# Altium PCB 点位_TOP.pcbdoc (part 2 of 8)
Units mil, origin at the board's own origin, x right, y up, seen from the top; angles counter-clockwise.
Board outline 5129 x 4161 mil, 8 copper layers (Top Layer, GND1, 内层2, VCC, 内层4, Inner5, GND2, Bottom Layer); 288 components, 452 nets, 2040 pads, 1119 vias.
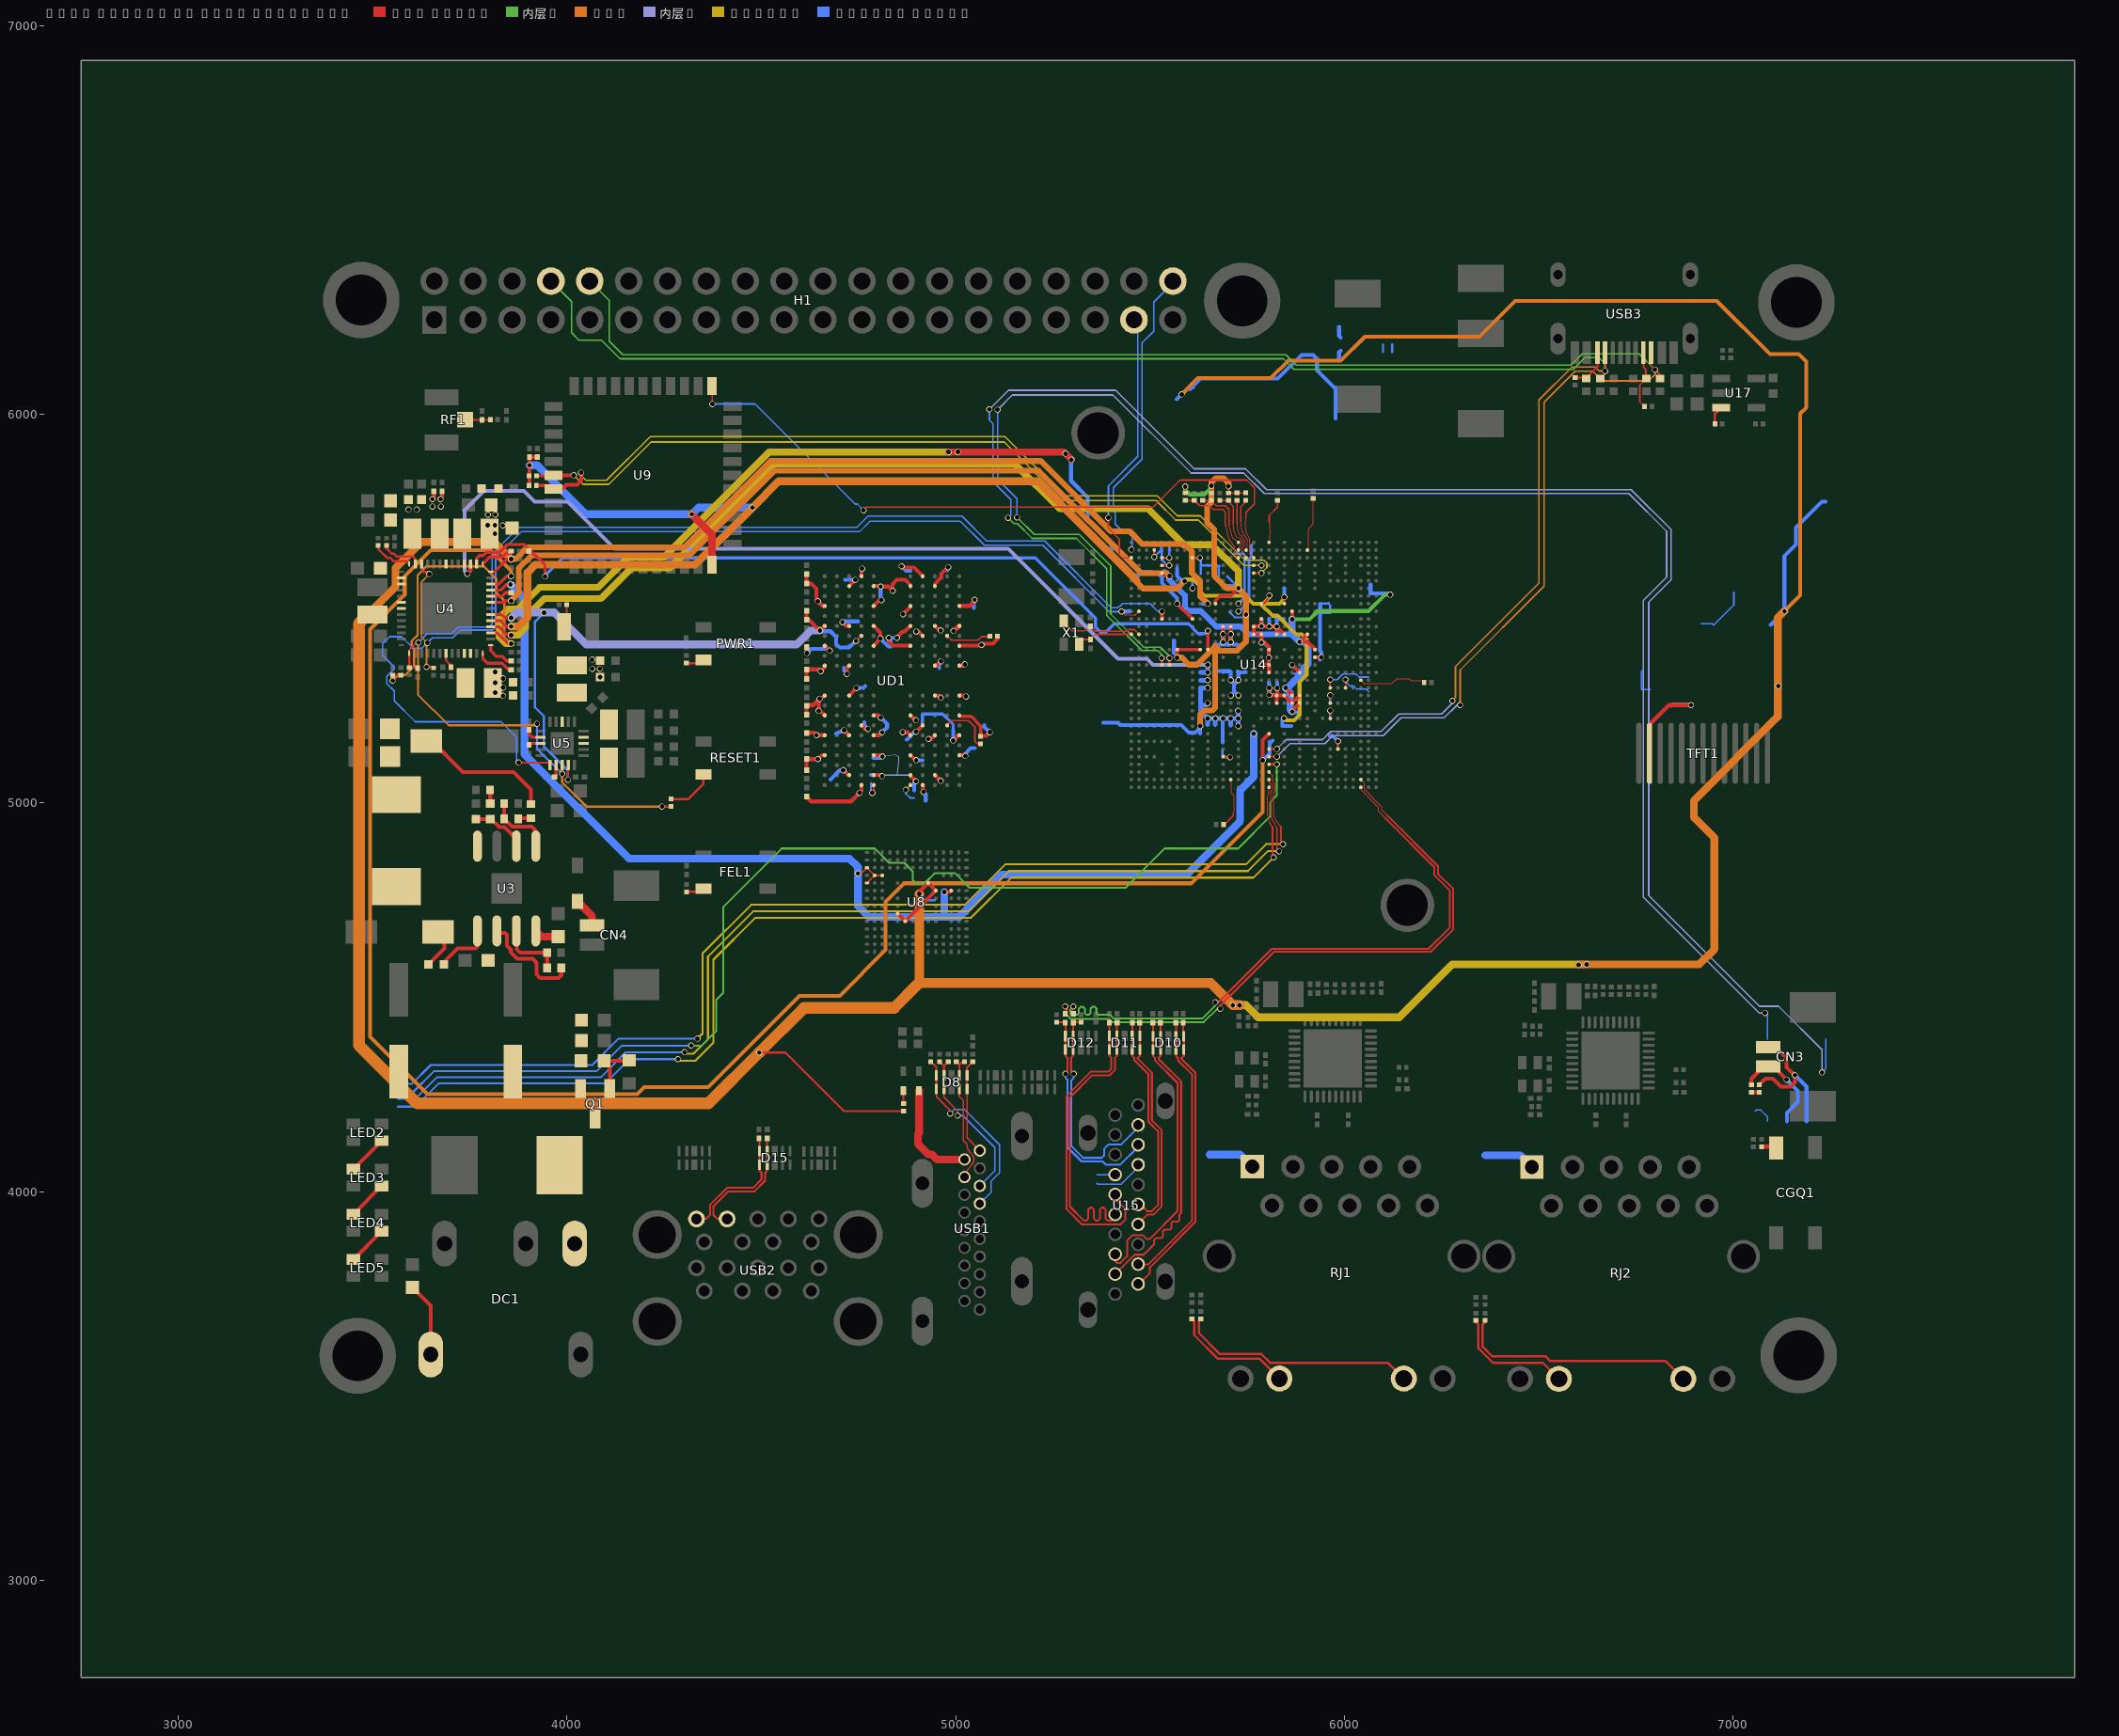
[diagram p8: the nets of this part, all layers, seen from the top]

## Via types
v1: diameter 15.75, hole 11.8, Top Layer to Bottom Layer, 496 vias
v2: diameter 15.7, hole 11.8, Top Layer to Bottom Layer, 335 vias
v3: diameter 15.75, hole 11.81, Top Layer to Bottom Layer, 279 vias
v4: diameter 24, hole 12, Top Layer to Bottom Layer, 9 vias

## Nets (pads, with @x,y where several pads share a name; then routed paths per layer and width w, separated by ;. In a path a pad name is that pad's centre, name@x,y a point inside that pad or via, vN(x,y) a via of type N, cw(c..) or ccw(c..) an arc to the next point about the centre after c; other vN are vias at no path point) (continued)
323-DCDC3: C87.2 C89.2 L8.2 U14.AA12 U14.AA13 U14.Y12 U14.Y13 | length 199.1
  Top Layer w10: v2(5688.24,5414.21) v2(5688.24,5434.21) U14.AA12@5688.24,5453.9 ; v2(5707.92,5414.21) v2(5707.92,5434.21) U14.Y12@5707.92,5453.9
  Bottom Layer w10: 5667.23,5407.31 v2@5686.23,5407.31 ; v2(5688.24,5434.21) v2(5688.24,5414.21) 5688.24,5409.32 v2@5686.23,5407.31 ; v2@5704.99,5407.14 5707.92,5410.07 v2(5707.92,5414.21) ; v2(5707.92,5434.21) v2(5707.92,5414.21) ; 5725.23,5407.31 5714.83,5407.31 v2(5707.92,5414.21) ; v2@5686.23,5407.31 5701.02,5407.31 v2(5707.92,5414.21)
  other v1: 4084.95,5323.63 4065,5345.34 4085.38,5345.34 4065,5369
323-DLDO1: C71.1 U5.12 | length 32.6
  Top Layer w8: C71.1@3968.5,5067 3972.09,5070.59 U5.12@3972.09,5098.08
323-RTCLDO: C73.1 U5.7 | length 43.8
  Top Layer w8: C73.1@3903,5188 3903,5177 3911,5169 3932.19,5169 U5.7@3932.43,5169.24
$1N3706: L2.1 U4.10 U4.11
$1N3718: L3.1 U4.33
$1N3723: L4.1 U4.30
$1N3725: C43.1 U4.7 | length 41.6
  Top Layer w6: U4.7@3689.11,5385.61 3689.11,5366.89 3701.75,5354.25 C43.1@3701.75,5349.22
$1N4703: R13.2 U4.39 | length 104.9
  Top Layer w6: R13.2@3514.47,5662.49 3514.47,5653.53 3537,5631 3545.49,5631 3554.49,5622 3587.96,5622 U4.39@3594.63,5615.33
$1N4773: C44.2 U4.41 U4.42
$1N4806: R14.2 U4.38 | length 105.5
  Top Layer w6: R14.2@3536,5662.49 3536,5655 3549,5642 3554,5642 3561.5,5634.5 3603.5,5634.5 3610.37,5627.63 U4.38@3610.37,5615.33
$1N4992: L5.2 U4.45 U4.46
$1N6251: L6.1 U5.18
$1N6517: L7.1 U5.19
$1N6728: L8.1 U5.3
$1N7320: C88.1 U5.8 | length 31.1
  Top Layer w8: C88.1@3903,5149.5 3906.99,5153.49 U5.8@3932.43,5153.49
$1N42597: LED1.1 R17.1 | length 59
  Top Layer w6: LED1.1@3992.63,5453.84 3999.51,5460.73 R17.1@3999.51,5510
$2N1846: R21.1 RESET1.3 | length 123.8
  Top Layer w6: R21.1@4268,5010.51 4312.51,5010.51 4351.32,5049.32 RESET1.3@4351.32,5073.68
$2N2360: R19.1 U14.V3 | length 162.3
  Top Layer w3: 5725.01,5720.45 5726.4,5700.33 5731.46,5688.13 5735.46,5687.29 5743.72,5675.93 5743.82,5663.67 5737.3,5657.15 5737.36,5656.88 5737.36,5640.84 U14.V3@5747.19,5631.01
  Top Layer w4: R19.1@5724.27,5778.76 5724.27,5720.73 5725,5720
$2N2431: R20.1 U14.V2 | length 136.5
  Top Layer w3: 5734,5724.93 5736.55,5705.39 5741.89,5689.5 5750.21,5678.07 5750.31,5665.03 5750.55,5664.3 5750.55,5662.51 U14.V2@5746.51,5651.79
  Top Layer w4: 5734,5725 5734,5762 5746.27,5774.27 R20.1@5746.27,5778.76
$2N32401: FEL1.3 R22.1 | length 46.7
  Top Layer w6: R22.1@4308,4771.49 4343.13,4771.49 FEL1.3@4351.32,4779.68
$2N32457: PWR1.3 R23.1 | length 47.4
  Top Layer w6: R23.1@4307.07,5360.18 4343.82,5360.18 PWR1.3@4351.32,5367.68
$3N7591: U14.AA29 | length 51.6
  Top Layer w4.5: U14.AA29@5687.91,5119.12 5688.77,5118.26 v3(5706.21,5118.26)
  Bottom Layer w6: 5685.92,5135.46 5686.92,5134.46 5686.92,5124.97 5693.63,5118.26 v3(5706.21,5118.26)
$3N7643: UD1.A5 | length 53.9
  Top Layer w4.5: v3(4871.92,5033.97) 4883.64,5045.69 UD1.A5@4883.64,5046.54
  Bottom Layer w4.5: v3(4871.92,5033.97) 4871.92,5023.97 4882.76,5013.13 4893.92,5013.13
$3N7644: UD1.A8 | length 49.9
  Top Layer w4.5: v3(4785.84,5025.97) 4789.16,5029.29 UD1.A8@4789.16,5046.54
  Bottom Layer w4.5: 4782.21,5052.45 4782.21,5029.6 v3(4785.84,5025.97)
$3N7648: R36.1 UD1.G2 | length 138
  Top Layer w4.5: UD1.G2@4978.13,5200.08 4990.04,5212 5033,5212 5049.92,5195.08 5049.92,5157.63 5054.42,5153.13 R36.1@5064.92,5153.13
$3N7649: R37.1 UD1.T2 | length 119
  Top Layer w4.5: UD1.T2@4978.13,5430.4 4989.56,5418.97 5057.92,5418.97 5066.92,5427.97 5086.08,5427.97 R37.1@5087.92,5429.81
$4N500: R41.2 U14.Y32 | length 129.9
  Top Layer w3: U14.Y32@5709.98,5059.57 5709.98,5025.76 5716.84,5018.9 5716.84,4985.06 5714.63,4973.87
  Top Layer w4: R41.2@5689.66,4944.85 5691.85,4944.85 5714.54,4967.54 5714.54,4974.38
$4N609: R42.1 U14.C19 | length 176.1
  Top Layer w3: U14.C19@6042.49,5316.01 6052.39,5306.11 6121.11,5306.11 6133.9,5318.9 6167.81,5318.9 6172.71,5314 6201.49,5314 R42.1@6205.49,5310
$4N713: R43.1 U14.R1 | length 119
  Top Layer w3: U14.R1@5806.29,5670.41 5807.09,5671.21 5810.05,5698.92 5809.6,5700.66 5807,5723.72 5806.92,5724.41 ; 5807,5722.99 5807.09,5722.9
  Top Layer w4: 5807,5722.99 5807,5723.72 5807,5740 5828,5761 R43.1@5828,5778.49
$5N3909: R123.2 U14.K2 | length 139.1
  Top Layer w3: U14.K2@5904.69,5650.71 5908.43,5654.45 5908.43,5705.75 5920,5717.32 R123.2@5920,5783.49
$6N1044: U14.G22 | length 38.7
  Top Layer w4: U14.G22@5963.82,5257.04 v1(5963.82,5277.04)
  Bottom Layer w6: 5963.49,5258.47 5963.82,5258.8 v1(5963.82,5277.04)
$6N1104: U14.G24 | length 39.8
  Top Layer w4: U14.G24@5963.82,5217.67 v1(5963.82,5237.67)
  Bottom Layer w6: 5963.49,5218 5963.49,5237.33 v1(5963.82,5237.67)
$6N1424: U14.F28 | length 45.2
  Top Layer w4: U14.F28@5983.52,5138.93 v1(5983.52,5158.93)
  Bottom Layer w10: 5963.51,5171.53 5970.91,5171.53 v1(5983.52,5158.93)
$6N1887: U14.G20 | length 129
  Top Layer w4: U14.G20@5963.83,5296.4 v1(5963.83,5317.4)
  Bottom Layer w4: v1(5963.83,5317.4) 5981.4,5317.4 5996,5332 6030,5332 6038,5324 6062.49,5324
$6N1980: U14.E20 | length 97.6
  Top Layer w4: U14.E20@6003.2,5296.41 v1(6003.2,5317.41)
  Bottom Layer w4: v1(6003.2,5317.41) 6003.2,5311.8 6014,5301 6024,5301 6032,5293 6056.49,5293 6063.49,5286
$6N3848: D7.2 R47.2 | length 33.5
  Top Layer w5: R47.2@4866,4226.51 D7.2@4866,4260
$6N3980: D8.1 D8.10 R48.2 USB1.13 | length 496.1
  Top Layer w4: D8.1@4950.63,4264.67 4950.63,4244.37 4986,4209 v1(4986,4201)
  Top Layer w5: R48.2@4936,4334.49 4950.63,4319.86 D8.10@4950.63,4299.33 D8.1@4950.63,4264.67
  Bottom Layer w4: v1(4986,4201) 4997,4212 5022,4212 5113,4121 5113,4049 5091,4027 5091,3998.11 USB1.13@5062.26,3969.36
$6N4130: D9.1 USB1.18 | length 274.7
  Top Layer w20: D9.1@4906,4260 4906,4151 4903,4148 4903,4123 4930,4096 4939,4096 4951.97,4083.03 USB1.18@5022.89,4083.03
$6N4341: D8.2 D8.9 R50.2 R52.2 USB1.15 | length 418.4
  Top Layer w4: D8.2@4970.3,4264.67 4970.3,4242.7 5005,4208 v1(5005,4196)
  Top Layer w5: R50.2@4959,4334.49 4970.3,4323.19 ; D8.2@4970.3,4264.67 D8.9@4970.3,4299.33 4970.3,4323.19 ; R52.2@4981,4334.49 4970.3,4323.79 4970.3,4323.19
  Bottom Layer w4: v1(5005,4196) 5019,4196 5101,4114 5101,4053.59 USB1.15@5062.26,4014.85
$6N4352: D8.4 D8.7 R51.2 R53.2 USB1.16 | length 336.3
  Top Layer w4: D8.4@5009.7,4264.67 5009.7,4245.3 5020,4235 5020,4132 5026.32,4125.68 cw(c5011.57,4114.53) 5030,4116 ccw(c5050.64,4117.64) 5036,4103 cw(c4999,4066) 5046,4089 cw(c5033.74,4083) 5046,4077 cw(c5009.34,4094.94) 5040,4068 ccw(c5103.16,4012.51) USB1.16@5022.89,4037.52
  Top Layer w5: R51.2@5002,4334.49 5009.7,4326.79 ; D8.4@5009.7,4264.67 D8.7@5009.7,4299.33 5009.7,4326.79 ; R53.2@5023,4334.49 5017.4,4334.49 5009.7,4326.79
$6N4414: D8.5 D8.6 R54.2 USB1.19 | length 248.4
  Top Layer w4: D8.5@5029.37,4264.68 5029.37,4138.68 USB1.19@5062.26,4105.79
  Top Layer w5: D8.5@5029.37,4264.68 D8.6@5029.37,4299.33 5029.37,4319.86 R54.2@5044,4334.49
$6N5317: C190.2 D10.1 D10.10 U15.1 | length 752.3
  Top Layer w5: U15.1@5469.51,3762.25 5471.41,3762.25 5500.01,3790.85 5500.01,3805.1 5617.01,3922.1 5617.01,4305.81 5581.2,4341.62 5581.2,4344.12 5586.52,4349.45 ; C190.2@5585.6,4435.1 5585.6,4401.06 D10.1@5586.52,4400.14 ; 5587.52,4349.6 D10.1@5587.52,4400.14
$6N5400: C191.2 D10.2 D10.9 U15.3 | length 711.8
  Top Layer w5: U15.3@5469.51,3813.45 5496.45,3813.45 5607.99,3924.99 5607.99,4302.08 5572.18,4337.89 5572.18,4344.12 5566.85,4349.45 D10.9@5566.85,4365.34 ; C191.2@5566.6,4435.1 5566.85,4434.86 D10.2@5566.85,4400.14 D10.9@5566.85,4365.48
$6N5519: C192.2 D10.4 D10.7 U15.4 | length 782.1
  Top Layer w5: U15.4@5410.51,3787.85 5460.51,3837.85 5483.85,3837.85 5511,3865 5511,3876 5516.1,3881.1 5530.1,3881.1 5533.71,3884.71 5533.71,3898.71 5537.32,3902.32 5551.32,3902.32 5554.92,3905.92 5554.92,3919.92 5558.53,3923.53 5572.53,3923.53 5576.14,3927.14 5576.14,3941.14 5580.01,3945.01 5580.01,4283.74 5522.13,4341.62 5522.13,4344.12 5527.45,4349.45 D10.7@5527.45,4365.34 ; C192.2@5526.6,4435.1 5527.45,4434.26 D10.4@5527.45,4400.14 D10.7@5527.45,4365.48
$6N5561: C193.2 D10.5 D10.6 U15.6 | length 778.3
  Top Layer w5: U15.6@5410.51,3839.05 5410.51,3821.35 5415.01,3816.85 5424.01,3816.85 5441.01,3833.85 5441.01,3873.85 5455.36,3888.2 5481.66,3888.2 5491.89,3877.97 5498.97,3877.97 5570.99,3949.99 5570.99,4280.01 5513.11,4337.89 5513.11,4344.12 5507.78,4349.45 D10.6@5507.78,4365.34 ; C193.2@5507.6,4435.1 5507.78,4434.93 D10.5@5507.78,4400.13 D10.6@5507.78,4365.48
$6N5603: C194.2 D11.1 D11.10 U15.7 | length 581.3
  Top Layer w5: U15.7@5469.51,3915.75 5469.51,3917.34 5493.01,3940.84 5508.74,3940.84 5530.01,3962.1 5530.01,4158.85 5505.01,4183.85 5505.01,4305.81 5468.79,4342.03 5468.79,4344.53 5474.11,4349.86 D11.10@5474.11,4365.75 ; C194.2@5473.6,4435.1 5474.1,4434.6 D11.1@5474.1,4400.56 D11.10@5474.1,4365.9
$6N5645: C195.2 D11.2 D11.9 U15.9 | length 561.9
  Top Layer w5: D11.9@5454.44,4365.75 5454.44,4349.86 5459.77,4344.53 5459.77,4338.3 5495.99,4302.08 5495.99,4180.12 5520.99,4155.12 5520.99,3965.84 5505.01,3949.85 5493.01,3949.85 5475.91,3966.95 U15.9@5469.51,3966.95 ; D11.9@5454.43,4365.9 D11.2@5454.43,4400.56 5454.43,4434.93 C195.2@5454.6,4435.1
$6N5687: C196.2 D11.4 D11.7 U15.10 | length 800.3
  Top Layer w5: U15.10@5410.51,3941.35 5410.51,3934.35 5402.01,3925.85 5391.01,3925.85 5386.01,3930.85 5386.01,3953.85 5381.01,3958.85 5376.01,3958.85 5371.01,3953.85 5371.01,3930.85 5366.01,3925.85 5361.01,3925.85 5356.01,3930.85 5356.01,3953.85 5351.01,3958.85 5346.01,3958.85 5341.01,3953.85 5341.01,3930.85 5336.01,3925.85 5330.01,3925.85 5294.01,3961.85 5294.01,4242.1 5351.74,4299.84 5396.74,4299.84 5409.72,4312.81 5409.72,4344.53 5415.04,4349.86 D11.7@5415.04,4365.75 ; D11.7@5415.03,4365.9 D11.4@5415.03,4400.56 5415.03,4434.53 C196.2@5415.6,4435.1
$6N5729: C197.2 D11.5 D11.6 U15.12 | length 804.3
  Top Layer w5: D11.6@5395.37,4365.75 5395.37,4349.86 5400.7,4344.53 5400.7,4316.54 5393.01,4308.85 5348.01,4308.85 5284.99,4245.84 5284.99,3956.01 5325.15,3915.85 5424.01,3915.85 5437.01,3928.85 5437.01,3954.85 5410.51,3981.35 U15.12@5410.51,3992.55 ; D11.6@5395.36,4365.9 D11.5@5395.36,4400.55 5395.36,4434.86 C197.2@5395.6,4435.1
$6N6451: C199.2 D12.2 D12.9 R61.2 U15.17 | length 579.2
  Top Layer w5: v1(5304,4303) 5304,4303.4 5296.97,4310.42 5296.97,4344.46 5302.3,4349.78 D12.2@5302.3,4365.67 D12.9@5302.3,4400.33 5302.3,4434.3 C199.2@5303,4435 5304.49,4436.49 R61.2@5323,4436.49
  Bottom Layer w5: v1(5304,4303) 5304,4292.63 5298,4286.63 5298,4117 5328,4087 5376,4087 5382,4093 5382,4110 5393,4121 5425,4121 5469.5,4165.5 U15.17@5469.5,4171.8
$6N6466: C198.2 D12.1 D12.10 R62.2 U15.15 | length 574.7
  Top Layer w5: R62.2@5260,4436.49 5280.51,4436.49 C198.2@5282,4435 5282.63,4434.37 D12.10@5282.63,4400.33 D12.1@5282.63,4365.67 5282.63,4349.78 5287.96,4344.46 5287.96,4310.42 5283,4305.47 v1(5283,4303)
  Bottom Layer w5: v1(5283,4303) 5283,4292.63 5288,4287.63 5288,4114.25 5324.27,4077.98 5378.02,4077.98 5387,4069 5423,4069 5469.5,4115.5 U15.15@5469.5,4120.7
$6N6553: U15.14 | length 47.1
  Bottom Layer w4: 5363.51,4043.53 5410.14,4043.53 U15.14@5410.5,4043.9
$6N6556: U15.13 | length 132.1
  Bottom Layer w4: 5363.51,4021.53 5366.05,4019 5426,4019 5469.5,4062.5 U15.13@5469.5,4069.5
$6N19248: C220.2 D15.5 D15.6 USB2.18 | length 333
  Top Layer w5: USB2.18@4333.52,3929.89 4357.87,3929.89 4367.98,3940 4367.98,3965.98 4412,4010 4479,4010 4500.96,4031.96 4500.96,4048.46 4495.63,4053.78 D15.6@4495.63,4069.67 D15.5@4495.63,4104.32 4495.63,4135.87 C220.2@4494.25,4137.25
$6N19249: C219.2 D15.4 D15.7 USB2.17 | length 333.2
  Top Layer w5: USB2.17@4412.26,3929.89 4387.11,3929.89 4377,3940 4377,3962.25 4415.73,4000.98 4482.73,4000.98 4509.97,4028.22 4509.97,4048.46 4515.3,4053.78 D15.7@4515.3,4069.67 D15.4@4515.3,4104.33 C219.2@4515.3,4137.2
$6N30377: R117.1 U17.3 | length 48.5
  Top Layer w6: R117.1@6953.26,5975.66 6953.26,6001.84 U17.3@6969.04,6017.62
$8N2040:  | length 139.3
  Bottom Layer w4: 6918,5461 6946.4,5461 6950,5457.4 7001.91,5509.31 7001.91,5541.73
$8N6741: LED2.1 LED3.3 | length 102.8
  Top Layer w10: LED3.3@3451.16,4058.17 3523.21,4130.22 LED2.1@3523.21,4131.12
$8N6795: LED3.1 LED4.3 | length 102.8
  Top Layer w10: LED4.3@3451.16,3941.91 3451.16,3942.81 LED3.1@3523.21,4014.86
$8N6805: LED4.1 LED5.3 | length 102.8
  Top Layer w10: LED5.3@3451.16,3825.65 3523.21,3897.7 LED4.1@3523.21,3898.6
$8N9148:  | length 71.3
  Bottom Layer w4: 6766.11,5340.31 6765,5339.2 6765,5291.51 6787,5291.51
$8N11462: TFT1.12 | length 253.2
  Top Layer w10: TFT1.12@6784.2,5128.67 6784.2,5201.2 6835,5252 v2(6892,5252)
  Bottom Layer w10: 6841,5250 6843,5252 v2(6892,5252)
$10N1043: RJ1.P1 | length 123.4
  Bottom Layer w20: 5653,4095.7 5732.06,4095.7 RJ1.P1@5763.4,4064.36
$10N3488: R79.2 RJ1.12 | length 309.3
  Top Layer w6: R79.2@5608,3672.49 5614,3666.49 5614,3631 5674,3571 5781.16,3571 RJ1.12@5833,3519.16
$10N3497: R80.1 RJ1.13 | length 614
  Top Layer w6: R80.1@5631,3672.49 5631,3671 5626,3666 5626,3636 5680,3582 5787,3582 5809,3560 6112.16,3560 RJ1.13@6153,3519.16
$11N1789: RJ2.P1 | length 131.9
  Bottom Layer w20: 6363,4093.7 6452.3,4093.7 RJ2.P1@6482.4,4063.6
$11N1876: R97.2 RJ2.12 | length 313.9
  Top Layer w6: R97.2@6338.37,3668.61 6338.37,3664.63 6345,3658 6345,3597 6382,3560 6510.4,3560 RJ2.12@6552,3518.4
$11N1882: R98.1 RJ2.13 | length 620.5
  Top Layer w6: R98.1@6362.37,3668.61 6362.37,3664.37 6356,3658 6356,3601 6381,3576 6518,3576 6530,3564 6826.4,3564 RJ2.13@6872,3518.4
$12N612: D2.2 DC1.1 Q1.3
$12N673: Q1.1 R1.1 R2.2 | length 142.2
  Top Layer w10: Q1.1@4110.4,4265.37 4110.4,4322.26 R1.1@4095.66,4337 4159.66,4337 R2.2@4160,4336.66
$12N750: C3.2 DC1.5 | length 191.9
  Top Layer w10: C3.2@3603,3753.47 3650.09,3706.39 DC1.5@3650.09,3581.04
$12N1163: C4.1 U3.1 | length 148.6
  Top Layer w10: C4.1@3683.99,4585 3683.99,4590.99 3719,4626 3765,4626 3770,4631 U3.1@3770,4670.98
$12N1491: C8.2 U3.4 | length 64
  Top Layer w20: U3.4@3920,4670.98 3934.51,4656.47 C8.2@3978,4656.47
$12N1559: C4.2 D4.2 L1.1 U3.8 | length 106.8
  Top Layer w10: C4.2@3643.99,4585 3685,4626.01 3685,4651.57 D4.2@3668.57,4668
$12N1618: C9.1 C10.1 U3.6 | length 144.9
  Top Layer w10: C10.1@3766,4959.01 C9.1@3803,4959.01 3804,4960 3826,4938 3840,4938 3870,4908 U3.6@3870,4889.02
$12N1697: C9.2 R7.1 | length 35.4
  Top Layer w10: R7.1@3802,5034 3803,5032.99 C9.2@3803,4999.01
$12N1966: R3.1 R5.2 | length 33.9
  Top Layer w10: R5.2@3874.85,4959.19 3876.66,4961 R3.1@3908,4961
$12N2016: R5.1 R8.2 U3.5 | length 172.6
  Top Layer w10: R8.2@3838.85,4998.18 R5.1@3838.85,4959.19 3859.04,4939 3910,4939 3920,4929 U3.5@3920,4889.02
$12N2052: R4.1 R6.2 U3.3 | length 168.6
  Top Layer w10: U3.3@3870,4670.98 3871,4669.98 3871,4624 3880.22,4614.78 R6.2@3949.27,4614.78 3949.27,4575.95 R4.1@3949.45,4575.77
$12N3300: CN4.2 D1.1 | length 77.7
  Top Layer w20: D1.1@4027,4746.84 4064.91,4708.92 CN4.2@4064.91,4684.8
$13N975: C245.2 R72.2 RF1.1 | length 65.1
  Top Layer w5: RF1.1@3738.02,5986 3738.24,5986.22 C245.2@3781.57,5986.22 R72.2@3803.06,5986.22
$13N1231:  | length 51.1
  Bottom Layer w4: 7057,4207.51 7059.49,4210 7071,4210 7089,4192 7089,4181.39
$13N1378: R77.1 R78.1 | length 20.1
  Top Layer w10: R77.1@7047.19,4255.75 7067.17,4255.75 R78.1@7067.26,4255.83
$13N1478: CN3.1 R77.2 | length 263.9
  Top Layer w10: R77.2@7047.19,4274.77 7047.19,4290.19 7079.2,4322.2 CN3.1@7090.91,4322.2 7103.8,4322.2 v2(7138,4288)
  Bottom Layer w10: v2(7138,4288) 7167,4259 7167,4231 7139,4203 7139,4181.39
$13N1485: CN3.2 R78.2 | length 373.6
  Top Layer w10: R78.2@7067.26,4274.85 7083.4,4291 7102,4291 7123,4270 7148,4270 7159,4281 v2(7159,4300) 7158,4300 7138,4320 7138,4344 7110.2,4371.8 CN3.2@7090.91,4371.8
  Bottom Layer w10: v2(7159,4300) 7189,4270 7189,4181.39
$13N1600:  | length 20.8
  Bottom Layer w5: 6123.19,6180.04 6123.19,6160.06 6123.76,6159.49
$13N1603:  | length 21.5
  Bottom Layer w5: 6099.76,6159.49 6099.76,6180.98
$13N2020:  | length 27.6
  Bottom Layer w10: 5986.49,6138 5986.49,6159.62 5990.72,6163.85
$13N2077:  | length 28.9
  Bottom Layer w10: 5986.49,6225 5986.49,6202.51 5990.99,6198
$13N5258: CGQ1.4 R125.1 | length 38.6
  Top Layer w10: R125.1@7073.62,4115.95 7107.74,4115.95 CGQ1.4@7110.88,4112.8
ADCIN0: U14.W9 | length 161.6
  Bottom Layer w6: 5716,5642 5736.51,5642 5738,5643.49 5743,5638.49 5743,5528.33
  Bottom Layer w7: v1(5727.62,5512.95) 5743,5528.33
ADCIN1: U14.W10 | length 186.5
  Bottom Layer w7: v1(5727.61,5493.27) 5730.27,5493.27 5755,5518 5755,5628 5760.49,5633.49 5760.49,5662.49 5762,5664
AGND: U14.AE3 | length 137
  Top Layer w6: U14.AE3@5609.5,5631.06 v1(5628.5,5631.06)
  Bottom Layer w6: v1(5628.5,5631.06) 5631.25,5628.31 5631.25,5611.25 ; 5631.25,5589.25 5631.25,5611.25 ; 5676.5,5583 5676.5,5607.51 ; 5679,5610 5676.5,5607.51 ; 5631.25,5611.25 5651.75,5611.25 5652,5611.5 5672.51,5611.5 5676.5,5607.51
ALDO1: C51.1 U4.13 | length 98.3
  Top Layer w8: U4.13@3783.6,5385.61 3784,5385.21 3784,5372 3796,5360 3833,5360 3850,5343 C51.1@3856.5,5343
ALDO2: C52.1 U4.14 | length 77.3
  Top Layer w8: U4.14@3803.97,5405.98 3803.97,5392.03 3819,5377 3834.25,5377 3845.25,5366 C52.1@3856.5,5366
ALDO3: C53.1 R11.1 R12.1 U4.16 U14.AE11 U14.AG9 | length 3149.8
  Top Layer w6: v1(3551.77,5315) R11.1@3551.77,5329.26 R12.1@3572.77,5329.26
  Top Layer w8: U4.16@3803.97,5437.48 3821.52,5437.48 3849,5410 v2(3856.5,5410)
  Top Layer w10: v2(5570.13,5512.95) U14.AE11@5609.5,5473.58
  Top Layer w18: v2(4982,5903) v2(5006,5903) 5279,5903 v2(5283,5899) 5298,5884 v2(5298,5883)
  VCC w6: v1(3551.77,5315) 3565.77,5329 3584,5329 3607,5352 3607,5395 3601,5401 3601,5417 3616,5432 3616,5586 3639,5609 3786,5609 3819,5576 3819,5541 3839,5521 3839,5427.5 v2(3856.5,5410)
  Inner5 w18: v2(3856.5,5410) 3843,5410 3826,5427 3826,5476 3849,5499 3874.46,5499 3930.46,5555 4081,5555 4159,5633 4250.46,5633 4520.46,5903 v2(4982,5903)
  Bottom Layer w10: v2(5298,5883) 5297,5882 5297,5829 5340,5786 5340,5730 5401,5669 5401,5644 5459,5586 5471,5586 5480,5595 5505,5595 5510,5590 5521,5590 5531,5580 5531,5566 5570.13,5526.87 v2(5570.13,5512.95)
ALDO4: C54.1 R19.2 R20.2 R30.2 R31.2 R32.2 U4.17 U14.AB9 U14.AD15 U14.AD25 U14.AG15 U14.W7 | length 4078.8
  Top Layer w4: R32.2@5591,5797.51 v1(5591,5814) ; R30.2@5658,5797.51 v1(5658,5816) ; v1(5702,5815) R31.2@5702,5797.51 R19.2@5724,5797.51 ; R19.2@5724.27,5797.78 R19.2@5724,5797.51 ; R20.2@5746.27,5797.78 5746,5797.51 R19.2@5724,5797.51
  Top Layer w8: U4.17@3803.97,5453.23 3825.77,5453.23 3844,5435 3853.5,5435 v2(3856.5,5432) ; U14.AG15@5570.13,5394.83 U14.AD15@5629.18,5394.84 ; U14.AB9@5668.54,5512.95 5668.54,5520.54 5681,5533 5708.29,5533 v1(5727.62,5552.32)
  Top Layer w10: v2(5570,5374) 5570,5394.71 U14.AG15@5570.13,5394.83
  内层2 w10: v1(5591,5814) 5591,5805 5602,5794 5640,5794 5658,5812 v1(5658,5816)
  VCC w15: v2(5570,5374) 5582,5374 5599.89,5356.11 5621.11,5356.11 5668,5403 ; v1(5629.19,5197.99) 5629.19,5228.19 5639,5238 5660,5238 5668,5246 5668,5403 ; v1(5702,5815) 5702,5823 5689,5836 5670,5836 5658,5824 v1(5658,5816) 5658,5773 5647,5762 5647,5722 5665,5704 5665,5585 5697.68,5552.32 v1(5727.62,5552.32) 5747,5532.94 v2(5747,5484.84) 5747,5415 5724,5392 5679,5392 5668,5403
  Inner5 w18: v2@3856.6,5432.1 3856.7,5432 3875,5432 3894,5451 3894,5478 3942,5526 4087,5526 ; 4090,5528 4167,5605 4265.46,5605 4533.46,5873 5152,5873 5268,5757 5495,5757 5587,5665 5659,5665 5727.62,5596.38 v1(5727.62,5552.32)
  Bottom Layer w5: 5704.51,5491 5717.51,5478 5740.16,5478 v2(5747,5484.84)
  Bottom Layer w6: 5699,5583 5727.62,5554.38 v1(5727.62,5552.32)
  Bottom Layer w8: 5699,5560 5719.94,5560 v1(5727.62,5552.32)
  Bottom Layer w10: 5379.92,5206.47 5380.26,5206.81 5417.92,5206.81 ; 5416.92,5205.81 5417.92,5206.81 ; 5562,5418 5562,5385.62 5570,5377.62 v2(5570,5374) ; 5629,5179 5629.19,5179.19 v1@5629.19,5193.19 ; v1(5629.19,5197.99) v1@5629.19,5193.19 ; 5417.92,5206.81 5423.76,5200.97 5580.22,5200.97 5600.19,5181 5617,5181 v1@5629.19,5193.19
ALDO-OUT: U14.AE7 | length 16.5
  Bottom Layer w7: 5609,5568 5609,5552.18 5609.18,5552 v1(5609.5,5552.32)
AP-NMI: R10.2 U4.37 U5.11 U14.AM10 | length 3321.8
  Top Layer w3: 5436,5483.76 5462,5483.76
  Top Layer w4: v1(5427,5492.76) 5436,5483.76 ; 5462,5483.76 5471.51,5493.26 U14.AM10@5471.7,5493.26
  Top Layer w5: v1(3876,5104) 3950.42,5104 U5.11@3956.34,5098.08
  Top Layer w6: U4.37@3626.12,5615.33 3626.12,5600.4 3632.51,5594 3641,5594 v2(3646,5589) ; v2(3639,5350) 3654.51,5350 R10.2@3657,5347.51
  VCC w4: v2(3641,5412) 3626.2,5426.8 3626.2,5569.2 v2(3646,5589)
  VCC w6: v2(3639,5350) 3639,5410 v2(3641,5412)
  Bottom Layer w4: v1(3876,5104) 3871,5109 3871,5169 3831,5209 3610,5209 3556,5263 3556,5288 3537,5307 3537,5326 3555,5344 3555,5351 3526,5380 3526,5410 3544,5428 3575,5428 3605,5398 3627,5398 v2(3641,5412) 3654,5425 3706,5425 3726,5445 3809,5445 3817,5453 3817,5632 3883,5698 4753,5698 4780,5725 5012,5725 5074,5663 5224,5663 5395,5492 5426.24,5492 v1(5427,5492.76)
  Bottom Layer w10: v1(5427,5492.76) 5445.76,5492.76 5447,5494
AP-RESET: C95.2 R9.2 R21.2 U4.1 U5.13 U14.AJ11 | length 3360.8
  Top Layer w4: U4.1@3594.63,5385.61 3594.63,5393.63 3614,5413 v2(3618,5413)
  Top Layer w5: U5.13@3987.84,5098.08 3987.84,5075.16 v1(3988,5075)
  Top Layer w6: U4.1@3594.63,5385.61 3595,5385.24 R9.2@3595,5348.51 3614.49,5348.51 C95.2@3616,5347 ; v2(4245,4991) 4267.51,4991 R21.2@4268,4991.49
  Top Layer w10: U14.AJ11@5530.76,5473.58 5531,5473.82 v1(5531,5493)
  VCC w5: v2(3618,5413) 3617,5412 3617,5279 3696,5200 3919,5200 v2(3923,5204)
  VCC w6: v1(3988,5075) 3988,5053 4050,4991 v2(4245,4991)
  Bottom Layer w4: v2(3618,5413) 3641,5436 3704,5436 3721,5453 3800,5453 3808,5461 3808,5641 3876,5709 4746,5709 4775,5738 5016,5738 5080,5674 5229,5674 5401,5502 5417,5502 5421,5506 5422.96,5506 5429.96,5513 5500,5513 5519,5494 v1@5529,5494
  Bottom Layer w5: v2(3923,5204) 3923,5140 v1(3988,5075)
AP-WAKE-BT: R69.2 U9.6 U14.U4 | length 2074.2
  Top Layer w4: U14.U4@5766.98,5611.39 v1(5786.98,5611.39)
  Top Layer w8: R69.2@3921.79,5841.7 3962.64,5841.7 U9.6@3966.94,5846
  Top Layer w10: U9.6@3965.94,5843 v1(4018,5843)
  Inner5 w4: v1(4018,5843) 4041,5820 4108,5820 4217,5929 5125,5929 5276,5778 5516,5778 5566,5728 5625,5728 5741.61,5611.39 v1(5786.98,5611.39)
AXP717-CC1: D24.2 R130.2 USB3.A5 | length 153.7
  Top Layer w4: R130.2@6772.49,6020 6772.49,6020.51 6760,6033 6760,6075.4 D24.2@6777,6092.4
  Top Layer w5: USB3.A5@6769.21,6158.7 6770,6157.91 6770,6121 6776,6115 D24.2@6776,6092.4
AXP717-CC2: D31.2 R129.2 USB3.B5 | length 108.6
  Top Layer w4: R129.2@6594,6094.51 6619.89,6094.51 D31.2@6622,6092.4
  Top Layer w5: D31.2@6621,6091.4 D31.2@6622,6092.4 6651.1,6121.5 USB3.B5@6651.1,6158.7
BLDO1: C59.1 C179.2 C180.2 R69.1 R70.1 U4.18 U9.22 U14.N9 U14.N24 U14.T9 | length 3909.8
  Top Layer w6: U14.T9@5786.67,5512.95 5791.95,5512.95 5807,5528 v1(5807,5534) ; U14.N9@5845.72,5512.95 v1(5845.72,5529.95)
  Top Layer w8: U4.18@3803.97,5468.97 3830.03,5468.97 3845,5454 v2(3856.5,5454)
  Top Layer w10: R70.1@3902.49,5817 3904,5818.51 R69.1@3904,5842.93 ; R69.1@3902.77,5841.7 R69.1@3904,5842.93 ; C179.2@3923.75,5889.75 C180.2@3903.75,5889.75 3904,5889.5 v2(3904,5869) R69.1@3904,5842.93
  Top Layer w20: v2(4321,5743) 4373.17,5690.83 U9.22@4373.17,5612.94
  VCC w15: 5464,5570 5482,5552 5570,5552 v2(5589,5571)
  VCC w20: v2(3856.5,5454) 3875,5454 3898.65,5477.65 3898.65,5593 3918.65,5613 4330,5613 v2(4477,5760) 4545,5828 5210,5828 5464,5574
  Inner5 w10: v2(5589,5571) 5593,5575 5612,5575 5628,5559 5628,5545 5640,5533 5746,5533 5766,5513 5784,5513 ; v1(5807,5534) 5807,5528.34 5791.66,5513 ; v2(5845,5218) 5850,5213 5871,5213 5885,5227 5885,5312 5903,5330 5903,5421.14 5890.14,5434 5876,5434 5828,5482 5815,5482 5784,5513 ; v1(5845.72,5529.95) 5845.72,5525.72 5833,5513 5791.66,5513 ; 5784,5513 5791.66,5513
  Bottom Layer w10: 5570,5604 5570,5584 5583,5571 v2(5589,5571) ; v2(5845,5218) 5841,5214 5841,5198 5863,5198 ; v1(5845.72,5529.95) 5846,5530.23 5846,5553
  Bottom Layer w20: v2(3904,5869) 3923,5869 4049,5743 v2(4321,5743) 4338,5760 v2(4477,5760)
BLDO2: C61.1 C136.2 C139.2 C140.2 U4.19 U5.14 UD1.F1 UD1.F12 UD1.G4 UD1.G9 UD1.T4 UD1.T9 UD1.U1 UD1.U12 | length 2047.9
  Top Layer w4: v3(4744,5416.74) UD1.T9@4757.66,5430.4
  Top Layer w5: v1(4003,5060) 4003.59,5060.59 U5.14@4003.59,5098.08
  Top Layer w8: U4.19@3803.97,5484.72 3832.28,5484.72 3840,5477 3855.5,5477 v2(3856.5,5476)
  Top Layer w10: C140.2@4616.92,5180.97 4635.44,5180.97 v3(4641.92,5174.49) UD1.F12@4663.17,5174.49 ; C139.2@4616.92,5495.97 4616.92,5471.47 4622.42,5471.47 4650.05,5443.84 v3(4651.01,5443.84) UD1.U12@4663.17,5455.99 ; UD1.G9@4757.66,5200.08 4766.77,5190.97 4773.92,5190.97 4774.26,5190.63 v3(4774.52,5190.63) ; v3(4898.3,5183.24) 4899.19,5183.24 4915.14,5199.19 UD1.G4@4915.14,5200.08 ; v3(4898.92,5440.97) 4904.57,5440.97 UD1.T4@4915.14,5430.4 ; v3(4993.92,5160.97) 5007.44,5174.49 UD1.F1@5009.63,5174.49
  Top Layer w12: v3(4994.92,5442.72) 4995.17,5442.97 4996.61,5442.97 UD1.U1@5009.63,5455.99
  内层4 w20: v2(3856.5,5476) 3870.5,5490 v2(3941,5490) 3968,5490 4050,5408 4591,5408 4626.84,5443.84 v3(4651.01,5443.84)
  Bottom Layer w6: v2(3941,5490) 3918,5467 3918,5246 3941,5223 3941,5145 4003,5083 v1(4003,5060)
  Bottom Layer w8: v3(4898.3,5183.24) 4915,5199.95 4915,5228.97 4966.92,5228.97 4993.92,5201.97 4993.92,5186.97
  Bottom Layer w10: v3@4640.4,5174.49 v3(4641.92,5174.49) ; v3(4651.01,5443.84) 4652.88,5441.97 4677.92,5441.97 4693.01,5426.89 4693.01,5409.07 4702.1,5399.97 4726.92,5399.97 4743.69,5416.74 v3(4744,5416.74) ; 4764.92,5207.97 4764.92,5200.23 v3(4774.52,5190.63) ; 4874.92,5162.97 4895.19,5183.24 v3(4898.3,5183.24) ; v3(4993.92,5160.97) 4993.92,5186.97
BLDO3: C63.1 U4.21 U14.AJ5 U14.J15 U14.K13 U14.L22 U14.M10 U14.M21 | length 3311.8
  Top Layer w6: U14.AJ5@5530.76,5591.69 5538.45,5584 v1(5550,5584)
  Top Layer w8: U4.21@3803.97,5516.22 3839.22,5516.22 3843,5520 v2(3856.5,5520)
  Top Layer w10: v2(5849,5296) 5865.41,5279.59 U14.M21@5865.41,5276.73 ; U14.M10@5865.41,5493.27 5866,5492.68 v2(5866,5473) ; v2(5866,5235) 5866,5237.94 U14.L22@5885.1,5257.04 ; v2(5885,5415) v2@5885.57,5415 ; U14.K13@5904.78,5434.21 v2@5885.57,5415 ; U14.J15@5924.46,5394.83 5925,5395.37 5905.37,5415 v2@5885.57,5415
  内层2 w10: v2(5866,5473) 5911,5473 5932,5494 6062,5494 6104,5536 v2(6118,5536)
  VCC w15: v2(3856.5,5520) 3876,5539.5 3876,5604 3909,5637 4315,5637 4533,5855 5214,5855 5478,5591 5543,5591 v1(5550,5584)
  Bottom Layer w5: 5870,5332 5882,5332
  Bottom Layer w10: 5537.78,5597.22 5537.78,5596.22 v1(5550,5584) ; v2(5866,5235) 5868,5233 5884,5233 ; 6067.51,5562 6067.51,5539 6115,5539 v2(6118,5536)
  Bottom Layer w15: v1(5550,5584) 5550,5574 5590,5534 5590,5503 5599,5494 5631,5494 5671,5454 5733.77,5454 5753.77,5434 5866,5434
  Bottom Layer w18: v2(5866,5235) 5861,5240 5861,5284 v2(5849,5296) 5853,5296 5888,5331 ; v2(5866,5473) 5866,5434 v2(5885,5415) 5896,5415 5907,5404 5907,5357 5882,5332
BLDO4: C65.1 U4.22 | length 56.3
  Top Layer w8: U4.22@3803.97,5531.97 3832.97,5531.97 3842,5541 C65.1@3856.5,5541
BOOT-SEL-ADC: R30.1 R33.2 U14.W1 | length 170.5
  Top Layer w3: 5703.56,5716.97 5712.83,5681.98 U14.W1@5726.58,5671.63
  Top Layer w4: R33.2@5636,5778.49 5656.51,5778.49 R30.1@5658,5777 ; R30.1@5658,5778.49 R30.1@5658,5777 ; 5703.64,5717 5703.64,5755.36 5694,5765 5670,5765 R30.1@5658,5777
BT-RESETN: U9.34 U14.U3 | length 1794.5
  Top Layer w3: 5746.83,5734.69 5745.9,5713.21 5747.83,5695.99 5756.79,5679.77 5757.05,5679.51 5757.05,5640.85 U14.U3@5766.89,5631.01
  Top Layer w4: v2(4374.17,6026.72) U9.34@4374.17,6076.06 ; v1(4763,5753) 4771,5761 5508,5761 5578,5831 5749,5831 5769,5811 5769,5770 5746.96,5747.96 5746.96,5734.04
  Bottom Layer w4: v2(4374.17,6026.72) 4484.28,6026.72 4742,5769 4747,5769 v1(4763,5753)
BT-WAKE-AP: R70.2 U9.7 U14.U5 | length 2158.4
  Top Layer w4: U14.U5@5766.98,5591.69 v1(5786.98,5591.69)
  Top Layer w8: R70.2@3921.51,5817 3960.51,5817 U9.7@3966.94,5810.57
  Top Layer w10: U9.7@3965.94,5807.57 3987.57,5807.57 3999,5819 4026,5819 4037,5830 v1(4037,5850)
  Inner5 w4: v1(4037,5850) 4037,5842 4049,5830 4102,5830 4215,5943 5127,5943 5280,5790 5519,5790 5570,5739 5630,5739 5744,5625 5793,5625 5801,5617 5801,5605.71 v1(5786.98,5591.69)
CAN-RX0: U14.AJ17 | length 4589.3
  Top Layer w6: v1(5530,5373) 5530,5356.23 U14.AJ17@5530.76,5355.47
  内层2 w4: v2(5135,5734) 5150,5719 5159,5719 5197,5681 5311,5681 5389,5603 5389,5482.58 5479.58,5392 5520.37,5392 5530,5382.37 v1(5530,5373)
  内层4 w4: v2(5087,6013) 5136,6062 5412,6062 5614,5860 5746,5860 5800,5806 6738,5806 6841,5703 6841,5575 6783,5517 6783,4762 7068,4477 7117,4477 7229,4365 v2(7229,4307)
  Bottom Layer w4: v2(5087,6013) 5087,5985 5096,5976 5096,5827 5142,5781 5142,5741 v2(5135,5734) ; v2(7229,4307) 7239,4317 7239,4392.61
CAN-TX0: U14.AH17 | length 4287.6
  Top Layer w6: v1(5550,5373) 5550,5355.91 U14.AH17@5550.44,5355.47
  内层2 w4: v2(5158,5735) 5158.34,5735 5202.34,5691 5318,5691 5399,5610 5399,5486 5483.85,5401.15 5526.85,5401.15 5550,5378 v1(5550,5373)
  内层4 w4: v2(5108,6012) 5146,6050 5405,6050 5606,5849 5741,5849 5794,5796 6732,5796 6829,5699 6829,5581 6769,5521 6769,4758 7067,4460 v2(7082,4460)
  Bottom Layer w4: v2(5108,6012) 5108,5833 5158,5783 v2(5158,5735) ; v2(7082,4460) 7089,4453 7089,4392.61
CLDO1: C60.2 U4.23 U8.C6 U8.M4 U8.N4 U8.P3 U8.P5 U14.U26 | length 3110.9
  Top Layer w5: v1(4749,4819) 4757.46,4819 U8.P3@4772.05,4833.59 U8.N4@4791.73,4813.9 ; U8.P5@4772.06,4794.22 U8.N4@4791.73,4813.9 ; U8.M4@4811.41,4813.9 U8.N4@4791.73,4813.9
  Top Layer w8: U4.23@3803.97,5547.71 3829.71,5547.71 3844,5562 v1(3855,5562)
  Top Layer w10: v1(4971,4771) 4985.06,4771 U8.C6@4988.59,4774.52
  Bottom Layer w20: v1(3855,5562) 3891,5526 3891,5126 4160,4857 4727,4857 4749,4835 v1(4749,4819) 4749,4735 4777,4707 4969.22,4707 ; v1(4971,4771) 4971,4708.78 4969.22,4707 ; v1(5766.98,5178.3) 5766.98,5067.98 5732,5033 5732,4953 5595,4816 5119,4816 5010,4707 4969.22,4707
CLDO2: C62.2 U4.24 U14.R26 | length 4619.5
  Top Layer w8: U4.24@3803.97,5563.46 3824.46,5563.46 3845,5584 v2(3856.5,5584)
  Top Layer w10: v2(5790,5110) 5790,5161.94 U14.R26@5806.35,5178.3
  VCC w10: v2(3856.5,5584) 3856.5,5597.5 3803.63,5650.37 3650.37,5650.37 3582.63,5582.63 3582.63,5535.58 3493.83,5446.78 3493.83,4398.17 3641,4251 4181,4251 4199,4269 4363.16,4269 4598.16,4504 4702,4504 4820,4622 4820,4746 4867.39,4793.39 5606.39,4793.39 5790,4977 v2(5790,5110)
  Bottom Layer w10: v2(5790,5110) 5808,5128 5808,5154 5815,5161
CLDO3: C64.2 R47.1 U4.26 U8.E6 U8.F5 U8.J10 U8.K9 U14.AC9 | length 12994.8
  Top Layer w5: v2(4495,4358) 4562,4358 4712.51,4207.49 R47.1@4866,4207.49
  Top Layer w8: U4.26@3803.98,5594.97 3813.97,5594.97 3847,5628 v2(3856.5,5628)
  Top Layer w10: U8.K9@4850.78,4715.48 U8.J10@4870.48,4695.78 4945.65,4770.96 ; v2(4907,4766) 4907,4771.69 U8.F5@4929.52,4794.22 4945.65,4778.09 4945.65,4770.96 ; U8.E6@4949.22,4774.52 4945.65,4770.96
  VCC w10: v2(5581.59,6051.1) 5623.49,6093 5811,6093 5856,6138 5991,6138 6053,6200 6348,6200 6440,6292 6958,6292 7095,6155 7169,6155 7188,6136 7188,6017 7173,6002 7173,5534.4 v1(7132,5493.4)
  VCC w15: v2(3856.5,5628) 3869,5628 3899,5658 4302,5658 4524,5880 5219,5880 5400,5699 5448,5699 5481,5666 5589.33,5666 5608,5647.33 5608,5592 5629,5571 5629,5532.82 v2@5648.87,5512.95
  VCC w20: 3470,5467 3559,5556 3559,5605 3625.75,5671.75 3812.75,5671.75 v2(3856.5,5628) ; v2(6603,4584) 6604,4585 v2(6623.08,4585) 6913,4585 6952,4624 6952,4910 6899,4963 6899,5006 7115,5222 7115,5476.4 v1(7132,5493.4)
  VCC w25: v2(4907,4766) 4907,4538 4906,4537 5656,4537 v2(5713,4480) v2(5731,4480)
  VCC w30: 3470,5467 3465,5462 3465,4377 3615,4227 4364,4227 v2(4495,4358) 4610,4473 4842,4473 4906,4537
  Inner5 w20: v2(5713,4480) v2(5731,4480) 5747,4480 5778,4449 6142,4449 6278,4585 v2(6623.08,4585)
  Bottom Layer w6: v2(4907,4766) 4922.75,4750.25 4946.75,4750.25 ; v2(7116.5,5301) 7116.5,5341
  Bottom Layer w10: 4899,4749 4899,4758 v2(4907,4766) ; 5569,6038.51 v2(5581.59,6051.1) 5599.49,6069 5607,6069 ; 5603,6065 5607,6069 ; 5611.23,6069 5607,6069 ; 5636,5513 v2(5648.82,5513) ; 5977,5989.51 5977,6066 5929.51,6113.49 5929.51,6143.49 5920,6153 5890,6153 5829,6092 5630,6092 5607,6069 ; 7097,5458.4 v1(7132,5493.4) 7132,5635 7162,5665 7162,5709 7228.4,5775.4 7238.14,5775.4
CLDO4: C66.2 U4.27 | length 86.4
  Top Layer w8: U4.27@3783.61,5615.33 3801.27,5633 3834,5633 3844,5643 3851.5,5643 C66.2@3856.5,5648
CPUSLDO: C35.2 U4.28 U14.AC15 | length 2148.2
  Top Layer w8: U4.28@3767.85,5615.33 3768,5615.49 3768,5630 3775,5637 3785,5637 3793,5645 3827,5645 3847,5665 3889.88,5665 3901,5653.88 3901,5649 C35.2@3902,5648 3908,5648 3944,5612 v2(3944,5583) ; U14.AC15@5648.87,5394.84 v2(5648.87,5443)
  Bottom Layer w8: v2(3944,5583) 3944,5586 3989,5631 5205,5631 5360,5476 5360,5453 5373,5440 5387,5440 5408,5461 5599,5461 5624,5436 5641.87,5436 v2(5648.87,5443)
CPUX-RX: D30.2 H1.10 U14.R29 USB3.B8 | length 4759
  Top Layer w5: U14.R29@5806.35,5119.25 v1(5826.35,5119.25) ; USB3.B8@6788.9,6158.7 6788.9,6125.1 v2(6799.2,6114.8) 6812,6102 D30.2@6812,6092.4
  内层2 w4: H1.10@4059,6343 4109,6293 4109,6188 4144,6153 5850,6153 5876,6127 6583,6127 6612,6156 6758,6156 v2@6799,6115
  VCC w4: v2(6298,5252) 6298,5342 6514,5558 6514,6031 6594,6111 6639,6111 6664,6086 6783,6086 6799.2,6102.2 v2(6799.2,6114.8)
  内层4 w4: v1(5826.35,5119.25) 5860.1,5153 5950,5153 5970,5173 6100,5173 6146,5219 6257,5219 6290,5252 v2(6298,5252)
CPUX-TX: D27.2 H1.8 U14.R28 USB3.A8 | length 4564.4
  Top Layer w5: U14.R28@5806.35,5138.93 v1(5826.35,5138.93) ; D27.2@6658,6092.4 6670.79,6105.19 USB3.A8@6670.79,6158.7
  内层2 w4: H1.8@3959,6343 4012,6290 4012,6210 4031,6191 4089,6191 4137,6143 5843,6143 5870,6116 6589,6116 6619,6146 6655,6146 6670.79,6130.21 v2(6670.79,6111.36)
  VCC w4: v2(6278,5263) 6286,5271 6286,5351 6501,5566 6501,6037 6586,6122 6645,6122 6655.64,6111.36 v2(6670.79,6111.36)
  内层4 w4: v1(5826.35,5138.93) 5850.43,5163 5944,5163 5965,5184 6095,5184 6140,5229 6250,5229 6278,5257 v2(6278,5263)
CPVDD: U14.AJ3 | length 47
  Top Layer w6: U14.AJ3@5530.76,5631.06 v1(5549.76,5631.06)
  Bottom Layer w6: v1(5549.76,5631.06) 5549.76,5658.76 5550,5659
CPVEE: U14.AJ4 U14.AK2 | length 128.5
  Top Layer w6: v1(5511,5633) 5511,5650.68 U14.AK2@5511.07,5650.75 ; U14.AJ4@5530.76,5611.38 v1(5549.76,5611.38)
  Bottom Layer w6: v1(5511,5633) 5529,5651 5529,5658.5 5531,5656.5 5531,5625 5544.62,5611.38 v1(5549.76,5611.38)
CTP-INT: U14.R31 | length 2857.8
  Top Layer w3: U14.R31@5806.45,5080.07 5816.25,5070.27 5816.25,5053.78 5820.04,5049.99 ; 5819.83,5050.17 5820.04,5049.99 ; 5832.63,4943.08 5824.98,4953.82 5819.66,4962.85 5818.36,4968.27 5818.36,5028.09 5822.59,5032.31 5822.59,5038.2 5822.46,5039.1 5822.44,5041.94 5821.91,5048.12 ; 5820.04,5049.99 5821.89,5048.44 5821.91,5048.12 ; 5820.04,5049.99 5821.91,5048.12
  Top Layer w4: 5833,4943 5837,4939 5837,4899 v1(5842,4894)
  Inner5 w5: v1(4336,4394) 4349,4407 4349,4613 4474,4738 5024,4738 5128,4842 5747,4842 5799,4894 v1(5842,4894)
  Bottom Layer w5: 3564.97,4277.99 3601.99,4277.99 3650,4326 4065,4326 4133,4394 v1(4336,4394)
CTP-RST: U14.R30 | length 2993
  Top Layer w5: U14.R30@5806.34,5099.56 v1(5826.34,5099.56)
  内层2 w5: v1(4320,4376) 4347,4376 4384,4413 4384,4493 4402,4511 4402,4732 4553,4883 4792.17,4883 4792.17,4882.83 4829,4846 4868,4846 4890,4824 4890,4802 4899,4793 4920,4793 4946,4819 4999,4819 5036,4782 5437,4782 5538,4883 5727,4883 5809,4965 5809,5002 5826.34,5019.34 v1(5826.34,5099.56)
  Bottom Layer w5: 3564.97,4258.31 3606.3,4258.31 3658,4310 4076,4310 4142,4376 v1(4320,4376)
CTP-SCK: U14.R32 | length 2855.5
  Top Layer w3: 5806.31,5054.67 5810.33,5049.68 5815.64,5045.2 5815.94,5041.65 5815.99,5034.9 5811.36,5030.28 5811.36,4969.02 5813.9,4957.57 5821.16,4946.84 5824.94,4937.72 ; 5806.45,5054.57 U14.R32@5806.45,5060.37
  Top Layer w4: 5825,4937.64 5827,4935.64 5827,4881 v1(5832,4876)
  Inner5 w5: v1(4303,4359) 4307,4355 4326,4355 4363,4392 4363,4605 4479,4721 5033,4721 5137,4825 5752,4825 5803,4876 v1(5832,4876)
  Bottom Layer w5: 3564.97,4238.62 3609.62,4238.62 3666,4295 4088,4295 4152,4359 v1(4303,4359)
CTP-SDA: U14.R33 | length 2832.6
  Top Layer w3: U14.R33@5805.67,5039.66 5803.57,5029.78 5803.88,5023.19 5801,5015.46 5801.46,5003.15 5801.31,4986.83 5801.77,4968.71 5808.16,4947.03
  Top Layer w4: 5807.95,4947.18 5812.64,4941.52 5815.32,4938.83 5815.32,4862.68 v1(5818,4860)
  Inner5 w5: v1(4286,4341) 4290,4337 4331,4337 4377,4383 4377,4597 4485,4705 5040,4705 5143,4808 5766,4808 v1(5818,4860)
  Bottom Layer w5: 3564.97,4218.94 3610.93,4218.94 3671,4279 4099,4279 4161,4341 v1(4286,4341)
DCDC1: C15.2 C16.2 L2.2 U14.W19 U14.W21 U14.Y19 U14.Y21 | length 182.7
  Bottom Layer w10: 5667,5339.5 5686.5,5339.5 5686.75,5339.25 5705.75,5339.25 5707.92,5337.08 v2(5707.92,5316.1) 5716.5,5307.52 5716.5,5304.99 ; v2(5707.92,5276.73) 5716.5,5285.3 5716.5,5287.83 ; 5725.53,5338.61 5727.61,5336.53 5727.61,5336 ; v2(5727.61,5276.73) 5716.5,5287.83 ; 5745.11,5338.47 5742.64,5336 5727.61,5336 ; 5716.5,5287.83 5716.5,5304.99 ; 5716.5,5304.99 v2(5727.61,5316.1) 5727.61,5336
  other v1: 3836,5276 3816,5284.37 3836,5296.99 3816,5309 3836,5320.54 3816,5337
DCDC2: C18.2 C25.2 C210.2 C218.2 C290.2 C291.2 L3.2 U14.J16 U14.L18 U14.L21 U14.M22 U14.N13 U14.N21 U14.P13 U14.P21 U14.P22 U14.R15 U14.R17 U14.R18 U14.T11 U14.T13 U14.U12 U14.U13 | length 964.7
  Top Layer w10: v1(3654,5782) 3658,5786 C210.2@3658,5802 ; v1(3675,5782) 3679,5786 C218.2@3679,5802 ; U14.T11@5786.67,5473.58 5786.67,5455.33 v1(5787,5455) ; v2(5787,5356) 5805.82,5356 U14.R17@5806,5355.82 ; U14.R18@5806.35,5335.78 U14.R17@5806.35,5355.47 U14.R17@5806,5355.82 ; v2(5807,5296) v2(5807,5278) 5808.27,5276.73 U14.P21@5826.04,5276.73 ; U14.P13@5826,5434.25 5826,5453.94 U14.N13@5845.72,5434.21 ; v1(5826,5454) v1(5807,5454) 5806,5455 v1(5787,5455) ; U14.P22@5826.04,5257.04 U14.P21@5826.04,5276.73 ; v2(5827,5296) 5827,5277.69 U14.P21@5826.04,5276.73 ; v2(5866,5355) 5866,5354.86 U14.L18@5885.09,5335.78 ; U14.L21@5885.09,5276.73 5865.41,5257.05 U14.N21@5845.72,5276.73 U14.P21@5826.04,5276.73 ; U14.J16@5924.46,5375.16 v2(5941,5375.16) ; v1(5787,5455) 5768.08,5455 U14.U12@5766.98,5453.9 U14.U13@5766.98,5434.21 U14.T13@5786.67,5434.21 5787,5433.88 v1(5787,5413) 5795,5413 5806.35,5401.65 U14.R15@5806.35,5394.84 5806,5394.49 v2(5806,5374) U14.R17@5806,5355.82
  Bottom Layer w6: 5938,5513 5959,5513 ; 5960,5514 5959,5513 ; 5963.5,5492 5963.5,5508.5 5959,5513
  Bottom Layer w10: v1(5787,5413) 5793,5413 5805.5,5400.5 5805.5,5392 5806,5391.5 v2(5806,5374) ; v1(5787,5455) 5787,5472.5 5787.75,5473.25 ; 5806,5309.5 5807,5308.5 v2(5807,5296) v2(5807,5278) 5826.5,5278 5827,5277.5 v2(5827,5296) 5827,5309.5 ; 5806.75,5473.25 5807,5473 v1(5807,5454) ; 5825.75,5473.25 5826,5473 ; v1(5826,5454) 5826,5473 ; 5844.75,5473.25 5844.5,5473 5826,5473 ; v2@5937.5,5369 5941,5372.5 v2(5941,5375.16) 5941,5387.5 5937.5,5391 5937.5,5491.5 ; 5938,5513 5938,5492 5937.5,5491.5 ; 5963.5,5492 5963,5491.5 5937.5,5491.5
  other v1: 3593,5755 3614,5755 3654,5763 3676,5763
DCDC3: C31.2 C33.2 C131.2 C146.2 C147.1 C148.2 C149.2 C150.2 C157.2 C158.2 C159.2 C160.2 C292.2 C293.2 L4.2 R36.2 R37.2 U4.29 U14.AA24 U14.AB24 U14.AC17 U14.AC18 U14.AC19 U14.AC20 U14.AC22 U14.AC24 U14.W23 U14.W24 U14.W25 U14.Y24 UD1.A4 UD1.A9 UD1.AA3 UD1.AA5 UD1.AA8 UD1.AA10 UD1.AB4 UD1.AB9 UD1.B3 UD1.B5 UD1.B8 UD1.B10 UD1.D1 UD1.D5 UD1.D8 UD1.D12 UD1.F3 UD1.F5 UD1.F8 UD1.F10 UD1.H1 UD1.H5 UD1.H8 UD1.H12 UD1.K1 UD1.K3 UD1.K10 UD1.K12 UD1.N1 UD1.N3 UD1.N10 UD1.N12 UD1.R1 UD1.R5 UD1.R8 UD1.R12 UD1.U3 UD1.U5 UD1.U8 UD1.U10 UD1.W1 UD1.W5 UD1.W8 UD1.W12 | length 5468
  Top Layer w4.5: R37.2@5104.43,5428.97 5104.43,5424.36 R37.2@5104.87,5423.92
  Top Layer w8: UD1.H1@5009.63,5225.67 5012.33,5222.97 5040.03,5222.97 5064.92,5198.08 R36.2@5064.92,5172.81
  Top Layer w10: v1(3744,5590) 3752.1,5598.1 U4.29@3752.1,5615.33 ; C157.2@4616.92,5015.97 4628.92,5003.97 4730.84,5003.97 v3(4752.84,5025.97) 4757.66,5030.79 UD1.A9@4757.66,5046.54 ; C131.2@4616.92,5082.97 4616.92,5108.97 4620.92,5112.97 v3(4645.84,5112.97) 4656.18,5123.31 UD1.D12@4663.17,5123.31 ; C147.1@4616.92,5227.97 4616.92,5251.97 4633.92,5251.97 v3@4647.61,5265.66 ; C149.2@4616.92,5320.97 4616.92,5343.97 4647.92,5343.97 v3(4652.92,5338.97) 4663.17,5349.22 UD1.N12@4663.17,5353.63 ; C150.2@4616.92,5403.47 4616.92,5386.97 v3(4617.92,5385.97) ; C160.2@4616.92,5589.97 4616.92,5564.97 4628.3,5564.97 4641.92,5551.35 4641.92,5522.97 v3(4645.92,5518.97) 4657.72,5507.17 UD1.W12@4663.17,5507.17 ; v3@4647.02,5236.54 v3(4647.61,5237.13) ; UD1.H12@4663.17,5225.67 4651.71,5237.13 v3(4647.61,5237.13) ; UD1.K12@4663.17,5276.85 4654.29,5267.97 v3(4649.92,5267.97) v3@4647.61,5265.66 ; UD1.R12@4663.17,5404.81 v3(4675.97,5392.01) ; v3(4709.01,5465.47) 4718.49,5455.99 UD1.U10@4726.16,5455.99 ; v3(4711.26,5084.43) 4711.38,5084.43 4723.68,5072.13 UD1.B10@4726.16,5072.13 ; v3(4712.92,5186.97) 4725.4,5174.49 UD1.F10@4726.16,5174.49 ; v3(4720.47,5332.41) 4720.47,5347.94 UD1.N10@4726.16,5353.63 ; UD1.K10@4726.16,5276.85 4726.16,5277.21 v3(4744.92,5295.97) ; UD1.AA10@4726.16,5558.35 4741.78,5573.97 v3(4741.92,5573.97) ; UD1.AB9@4757.66,5583.94 4757.66,5601.57 v3(4759.28,5603.19) ; UD1.B8@4789.16,5072.13 4807.76,5072.13 v3(4810.92,5068.97) ; UD1.D8@4789.16,5123.31 4808.58,5123.31 v3(4811.92,5119.97) ; UD1.F8@4789.16,5174.49 4803.4,5174.49 v3(4810.85,5181.94) ; UD1.H8@4789.16,5225.67 4801.7,5225.67 v3(4807.57,5219.8) ; UD1.R8@4789.16,5404.81 4789.16,5405.29 4806.84,5422.97 v3(4806.84,5423.21) 4806.84,5438.31 UD1.U8@4789.16,5455.99 ; UD1.W8@4789.16,5507.17 4803.96,5521.97 v3(4808.92,5521.97) ; UD1.AA8@4789.16,5558.35 4805.54,5558.35 v3(4806.92,5556.97) 4826.92,5556.97 v3(4837.92,5545.97) 4837.92,5562.97 4848.94,5574 4870.58,5574 4883.64,5560.94 UD1.AA5@4883.64,5558.35 ; v3(4827.92,5424.97) 4827.92,5414.81 4837.92,5404.81 UD1.R5@4883.64,5404.81 ; v3(4848.92,5424.97) 4848.92,5425.97 4863.94,5441 4868.64,5441 UD1.U5@4883.64,5455.99 ; v3(4860.92,5608.97) 4863.92,5605.97 4893.11,5605.97 UD1.AB4@4915.14,5583.94 ; v3(4863.92,5181.97) 4876.16,5181.97 UD1.F5@4883.64,5174.49 ; v3(4864.92,5485.97) 4883.64,5504.69 UD1.W5@4883.64,5507.17 ; UD1.B5@4883.64,5072.13 4883.64,5070.25 v3(4897.92,5055.97) ; UD1.D5@4883.64,5123.31 4896.98,5109.97 v3(4898.92,5109.97) ; UD1.H5@4883.64,5225.67 4896.34,5212.97 4897.92,5212.97 4897.92,5212.83 v3(4898.08,5212.83) ; UD1.A4@4915.14,5046.54 4916.14,5045.54 4916.14,5033.75 4916.92,5032.97 4916.92,5029.41 v3(4917.61,5028.72) ; v3@4929.92,5164.94 4929.92,5162.97 4935.12,5162.97 UD1.F3@4946.64,5174.49 ; UD1.B3@4946.64,5072.13 4961.8,5056.97 v3(4961.92,5056.97) ; UD1.K3@4946.64,5276.85 4955.96,5276.85 v3(4961.84,5270.97) ; UD1.N3@4946.64,5353.63 4950.82,5353.63 v3(4962.16,5364.97) ; UD1.U3@4946.64,5455.99 4958.66,5443.97 v3(4961.92,5443.97) ; UD1.AA3@4946.64,5558.35 4946.64,5563.69 4962.92,5579.97 4962.92,5588.97 v3(4980.92,5606.97) ; UD1.D1@5009.63,5123.31 5022.58,5123.31 v3(5024.92,5120.97) ; UD1.K1@5009.63,5276.85 5023.96,5276.85 v3@5026.84,5273.97 ; UD1.N1@5009.63,5353.63 5020.63,5353.63 v3(5024,5357) ; UD1.R1@5009.63,5404.81 5064.75,5404.8 v3(5066.92,5406.97) 5070.08,5410.13 5096.08,5410.13 5106.92,5420.97 5106.92,5428.48 R37.2@5106.43,5428.97 ; UD1.W1@5009.63,5507.17 5036.82,5507.17 5048.92,5519.27 v3(5048.92,5522.97) ; R36.2@5064.92,5172.81 5078.76,5172.81 v3(5087.92,5181.97) ; v3(4647.61,5237.13) v3@4647.61,5265.66
  内层4 w3: v3(4811.92,5119.97) 4843,5125 4853,5120 4853,5109 4849.64,5072
  内层4 w4: v3(4810.92,5068.97) 4813.94,5072 4849.64,5072 4881.89,5072 v3(4897.92,5055.97)
  内层4 w10: v1(3744,5590) 3737,5597 3737,5753 3787,5803 3889,5803 3917,5775 4002,5775 4123,5654 5135,5654 5418,5371 5492,5371 5507.58,5355.42 v3(5648.55,5355.42)
  Bottom Layer w8: 4712.92,5348.97 4712.92,5339.96 v3(4720.47,5332.41) ; v3(4827.92,5424.97) v3(4848.92,5424.97) ; 4957.92,5345.97 4957.92,5360.73 v3(4962.16,5364.97) ; 4978.78,5598.2 4978.78,5604.84 v3(4980.92,5606.97)
  Bottom Layer w10: v3(4617.92,5385.97) 4628.94,5397 4670.98,5397 v3(4675.97,5392.01) ; 4678.5,5060.67 4701.8,5083.97 4710.8,5083.97 v3(4711.26,5084.43) ; 4693,5178.5 v3(4712.92,5186.97) ; v3(4709.01,5465.47) 4710.85,5467.31 4749.12,5467.31 ; 4715.92,5573.97 v3(4741.92,5573.97) ; v3(4744.92,5295.97) 4763.08,5295.97 4767.92,5300.81 ; 4782.21,5072.13 4807.76,5072.13 v3(4810.92,5068.97) ; 4788.76,5115.97 4807.92,5115.97 v3(4811.92,5119.97) ; v3(4806.84,5423.21) 4827.37,5402.68 4833.12,5402.68 4833.12,5419.77 v3(4827.92,5424.97) ; v3(4806.92,5556.97) 4806.92,5523.97 v3(4808.92,5521.97) ; v3(4807.57,5219.8) 4824.08,5203.29 4824.08,5195.17 v3(4810.85,5181.94) ; v3(4860.92,5608.97) 4872.92,5596.97 4884.08,5596.97 ; 4893.92,5032.81 4893.92,5051.97 v3(4897.92,5055.97) ; v3(4898.92,5109.97) 4914.92,5109.97 ; v3(4917.61,5028.72) 4923.26,5023.07 4923.26,5006.06 ; v3(5024.92,5120.97) 5024.92,5126.97 5039.08,5141.13 5048.92,5141.13 ; 5047.42,5501.97 5047.42,5521.47 v3(5048.92,5522.97) ; 5073.76,5200.97 5073.76,5196.13 v3(5087.92,5181.97) ; 5687,5155.51 5687,5216.7 v3(5687.92,5217.62)
  Bottom Layer w12: 5630,5316 v3(5648.55,5316.05) ; 5630,5336 5648.28,5336 5648.55,5335.73 v3(5648.55,5355.42) ; 5648,5202 5648.55,5202.55 v3(5648.55,5217.62) ; v3(5648.55,5256.99) 5643.55,5252 5630.5,5252 ; v3(5648.55,5296.36) 5648.2,5296 5630,5296 5630,5252.5 5630.5,5252 ; 5668,5202 5668.23,5202.23 v3(5668.23,5217.62) ; 5708,5201 5708,5217.22 v3(5707.6,5217.62) ; v3(5727,5237) 5727.29,5236.71 v3(5727.29,5217.62) ; v3(5727.3,5197.94) v3(5727.29,5217.62) ; 5630.5,5252 5630.5,5235.66 v3(5648.55,5217.62) ; v3(5648.55,5217.62) v3(5668.23,5217.62) ; v3(5668.23,5217.62) v3(5687.92,5217.62) v3(5707.6,5217.62) ; v3(5707.6,5217.62) v3(5727.29,5217.62)
  other v1: 3815.02,5693 3835,5714 3796,5715 3815,5715 3797,5742 3816,5742
  other v3: 4929.85,5164.94 5026.92,5273.97 5648.55,5335.73
DCIN-5V: C5.2 C6.2 D3.1 L1.2 R3.2 | length 359.3
  Top Layer w10: D3.1@3638.43,5160 3652.57,5160 3732.57,5080 3863,5080 3908,5035 R3.2@3908,4997
DCIN-12V: C1.2 C2.2 C7.2 Q1.2 R1.2 R4.2 U1.1 U2.1 U3.2 | length 294.6
  Top Layer w10: U3.2@3820,4652 U3.2@3820,4670.98 3824.98,4666 3841,4666 3846,4661 3846,4633 3856,4623 3856,4616 3873,4599 3912,4599 3922,4589 3922,4559 3931,4550 3979,4550 3985.45,4556.45 R4.2@3985.45,4575.77
DCXO-XIN: C99.2 U14.AM13 X1.1 | length 224.2
  Top Layer w4: X1.1@5278,5468.46 5278,5463.76 5299,5442.76 5333.96,5442.76 C99.2@5346.35,5455.15 5359.49,5442 5439,5442 5443,5446 5459.91,5446 U14.AM13@5471.7,5434.21
DCXO-XOUT: C98.2 U14.AN13 X1.3 | length 144.7
  Top Layer w4: X1.3@5318,5408.46 5330.29,5420.76 C98.2@5347,5420.76 5360.46,5434.21 U14.AN13@5452.02,5434.21
DDR-PARA-SEL-ADC1: R31.1 R34.2 U14.W2 | length 168.2
  Top Layer w3: 5713.91,5717.67 5717.23,5700.13 5724.34,5682.99 5731.68,5681.44 5737.24,5673.79 5737.3,5666.34 5727.49,5656.53 U14.W2@5727.49,5650.71
  Top Layer w4: R34.2@5680,5778.49 R31.1@5702,5778.49 5702,5775 5714,5763 5714,5717.81
DDR-PARA-SEL-ADC2: R32.1 R35.2 U14.W3 | length 243.1
  Top Layer w3: 5696.07,5712.34 5696.1,5712.2 5703.04,5679.34 5717.45,5658.68 5717.68,5640.82 U14.W3@5727.49,5631.01
  Top Layer w4: R32.1@5591,5778.49 R35.2@5614,5778.49 5627.49,5765 5653,5765 5663,5755 5687,5755 5694,5748 5694,5714.3 5696.1,5712.2 5696.23,5712.07
DSP-UART-RX: H1.40 U14.AN2 | length 782.9
  Bottom Layer w4: v2(5452,5652) 5454,5654 5454,5688 5445,5697 5431.61,5697 5411,5717.61 5411,5747 5406,5752 5406,5811 5480,5885 5480,6184 5510,6214 5510,6289 5559,6338 H1.40@5559,6343
DSP-UART-TX: H1.37 U14.AN3 | length 687.2
  Top Layer w4: v2(5393,5734) 5393,5707 5421,5679 5421,5642 5431.94,5631.06 U14.AN3@5452.02,5631.06
  Bottom Layer w4: v2(5393,5734) 5393,5816 5469,5892 5469,6005.57 ; H1.37@5459,6243 5469,6233 5469,6005.57 ; 5469,6009 5469,6005.57
EDP-AUXN: C199.1 U14.C33 | length 1642.4
  Top Layer w3: U14.C33@6042.49,5040.4 6044.28,5038.61 6044.28,5032.46 6088,4988.74 6088,4979 6106,4961 6106,4960
  Top Layer w5: C199.1@5303,4457.5 5299,4461.5 5299,4472.5 v1(5303,4476.5) ; v1(5668,4487) 5676.25,4487 5814.25,4625 6217,4625 6271,4679 6271,4775.25 6232,4814.25 6232,4834 6106,4960
  内层2 w5: v1(5303,4476.5) 5295,4468.5 5295,4460 5300,4455 5312.28,4455 5317.28,4460 5317.28,4471 5322.28,4476 5327.28,4476 5332.28,4471 5332.28,4460 5337.28,4455 5342.28,4455 5347.28,4460 5347.28,4471 5352.28,4476 5357.28,4476 5362.28,4471 5362.28,4460 5367.28,4455 5397,4455 5406.62,4445.38 5634.62,4445.38 5668,4478.75 v1(5668,4487)
EDP-AUXP: C198.1 U14.C32 | length 1635.2
  Top Layer w3: U14.C32@6042.49,5060.11 6052.29,5050.31 6052.29,5036.35 6051.78,5035.84 6051.79,5034.86 6097,4989.65 6097,4981.75 6112.38,4966.38
  Top Layer w5: C198.1@5282,4457.5 5286,4461.5 5286,4472.5 v1(5282,4476.5) ; v1(5681,4471) 5681,4479 5819,4617 6221.75,4617 6280.02,4675.27 6280.02,4778.98 6241.02,4817.98 6241.02,4837.73 6112.38,4966.38
  内层2 w5: v1(5282,4476.5) 5285.98,4472.52 5285.98,4455.27 5297.25,4444 5395.25,4444 5402.89,4436.36 5638.36,4436.36 5674,4472 5680,4472 v1(5681,4471)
